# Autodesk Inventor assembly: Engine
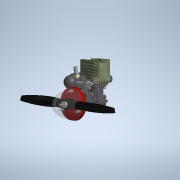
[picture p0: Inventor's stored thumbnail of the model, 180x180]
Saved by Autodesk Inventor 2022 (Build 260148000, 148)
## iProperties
Created: 2012-08
Part Number: Engine
Document SubType Name: Assembly
Designer: John
Author: John
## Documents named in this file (37)
- C:\Users\helfenj\Desktop\Ex_Files_Autodesk_Inventor_2022_Essential_Training\Exercise Files\01_Basic concepts\01_03\Engine.iam
- C:\Users\helfenj\Desktop\Ex_Files_Autodesk_Inventor_2022_Essential_Training\Exercise Files\01_Basic concepts\01_03\Engine Block.ipt
- C:\Users\helfenj\Desktop\Ex_Files_Autodesk_Inventor_2022_Essential_Training\Exercise Files\01_Basic concepts\01_03\Crankshaft.ipt
- C:\Users\helfenj\Desktop\Ex_Files_Autodesk_Inventor_2022_Essential_Training\Exercise Files\01_Basic concepts\01_03\Pulley Shaft.ipt
- C:\Users\helfenj\Desktop\Ex_Files_Autodesk_Inventor_2022_Essential_Training\Exercise Files\01_Basic concepts\01_03\Sleeve.ipt
- C:\Users\helfenj\Desktop\Ex_Files_Autodesk_Inventor_2022_Essential_Training\Exercise Files\01_Basic concepts\01_03\Piston Shaft.ipt
- C:\Users\helfenj\Desktop\Ex_Files_Autodesk_Inventor_2022_Essential_Training\Exercise Files\01_Basic concepts\01_03\Piston.ipt
- C:\Users\helfenj\Desktop\Ex_Files_Autodesk_Inventor_2022_Essential_Training\Exercise Files\01_Basic concepts\01_03\Piston Pin.ipt
- C:\Users\helfenj\Desktop\Ex_Files_Autodesk_Inventor_2022_Essential_Training\Exercise Files\01_Basic concepts\01_03\Crank Arm.ipt
- C:\Users\helfenj\Desktop\Ex_Files_Autodesk_Inventor_2022_Essential_Training\Exercise Files\01_Basic concepts\01_03\Face Plate.ipt
- C:\Users\helfenj\Desktop\Ex_Files_Autodesk_Inventor_2022_Essential_Training\Exercise Files\01_Basic concepts\01_03\washer4.ipt
- C:\Users\helfenj\Desktop\Ex_Files_Autodesk_Inventor_2022_Essential_Training\Exercise Files\01_Basic concepts\01_03\Screw Lock.ipt
- C:\Users\helfenj\Desktop\Ex_Files_Autodesk_Inventor_2022_Essential_Training\Exercise Files\01_Basic concepts\01_03\Beveled Sleeve.ipt
- C:\Users\helfenj\Desktop\Ex_Files_Autodesk_Inventor_2022_Essential_Training\Exercise Files\01_Basic concepts\01_03\Clutch Housing.ipt
- C:\Users\helfenj\Desktop\Ex_Files_Autodesk_Inventor_2022_Essential_Training\Exercise Files\01_Basic concepts\01_03\Brake Pad.ipt
- C:\Users\helfenj\Desktop\Ex_Files_Autodesk_Inventor_2022_Essential_Training\Exercise Files\01_Basic concepts\01_03\Clutch Sleeve14.ipt
- C:\Users\helfenj\Desktop\Ex_Files_Autodesk_Inventor_2022_Essential_Training\Exercise Files\01_Basic concepts\01_03\Clutch Bearing.ipt
- C:\Users\helfenj\Desktop\Ex_Files_Autodesk_Inventor_2022_Essential_Training\Exercise Files\01_Basic concepts\01_03\Clutch Sleeve11.ipt
- C:\Users\helfenj\Desktop\Ex_Files_Autodesk_Inventor_2022_Essential_Training\Exercise Files\01_Basic concepts\01_03\Carburetor.iam
- C:\Users\helfenj\Desktop\Ex_Files_Autodesk_Inventor_2022_Essential_Training\Exercise Files\01_Basic concepts\01_03\Heat Sink.ipt
- C:\Users\helfenj\Desktop\Ex_Files_Autodesk_Inventor_2022_Essential_Training\Exercise Files\01_Basic concepts\01_03\Starter Cover.ipt
- C:\Users\helfenj\Desktop\Ex_Files_Autodesk_Inventor_2022_Essential_Training\Exercise Files\01_Basic concepts\01_03\Horseshoe Clip.ipt
- C:\Users\helfenj\Desktop\Ex_Files_Autodesk_Inventor_2022_Essential_Training\Exercise Files\01_Basic concepts\01_03\ANSI B18.3 - 3-48 UNC - 0.375(31).ipt
- C:\Users\helfenj\Desktop\Ex_Files_Autodesk_Inventor_2022_Essential_Training\Exercise Files\01_Basic concepts\01_03\ANSI B18.3 - 2-56 UNC - 0.375(31).ipt
- C:\Users\helfenj\Desktop\Ex_Files_Autodesk_Inventor_2022_Essential_Training\Exercise Files\01_Basic concepts\01_03\Muffler.ipt
- C:\Users\helfenj\Desktop\Ex_Files_Autodesk_Inventor_2022_Essential_Training\Exercise Files\01_Basic concepts\01_03\ANSI B18.3 - 4-40 UNC - 0.875(31).ipt
- C:\Users\helfenj\Desktop\Ex_Files_Autodesk_Inventor_2022_Essential_Training\Exercise Files\01_Basic concepts\01_03\Muffler Tip.ipt
- C:\Users\helfenj\Desktop\Ex_Files_Autodesk_Inventor_2022_Essential_Training\Exercise Files\01_Basic concepts\01_03\Starter Handle.ipt
- C:\Users\helfenj\Desktop\Ex_Files_Autodesk_Inventor_2022_Essential_Training\Exercise Files\01_Basic concepts\01_03\ANSI B18.3 - 1-64 UNC - UNC - 0.25(1).ipt
- C:\Users\helfenj\Desktop\Ex_Files_Autodesk_Inventor_2022_Essential_Training\Exercise Files\01_Basic concepts\01_03\Clutch Prop Mount.ipt
- C:\Users\helfenj\Desktop\Ex_Files_Autodesk_Inventor_2022_Essential_Training\Exercise Files\01_Basic concepts\01_03\Prop Mount.ipt
- C:\Users\helfenj\Desktop\Ex_Files_Autodesk_Inventor_2022_Essential_Training\Exercise Files\01_Basic concepts\01_03\Prop.ipt
- C:\Users\helfenj\Desktop\Ex_Files_Autodesk_Inventor_2022_Essential_Training\Exercise Files\01_Basic concepts\01_03\Cone.ipt
- C:\Users\helfenj\Desktop\Ex_Files_Autodesk_Inventor_2022_Essential_Training\Exercise Files\01_Basic concepts\01_03\Crankshaft Cover.ipt
- C:\Users\helfenj\Desktop\Ex_Files_Autodesk_Inventor_2022_Essential_Training\Exercise Files\01_Basic concepts\01_03\ANSI B18.3 - 10-24 UNC - UNC - 0.5(1).ipt
- C:\Users\helfenj\Desktop\Ex_Files_Autodesk_Inventor_2022_Essential_Training\Exercise Files\01_Basic concepts\01_03\ANSI B18.2.2 - 1_4 - 20(3).ipt
- C:\Users\helfenj\Desktop\Ex_Files_Autodesk_Inventor_2022_Essential_Training\Exercise Files\01_Basic concepts\01_03\ASME B18.21.1 - No. 10. Carbon Steel(4).ipt
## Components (50 placed, 36 different names)
1. Engine Block:1 — Mate:1, Mate:2, Insert:1, Mate:8, Insert:2, Mate:16, Mate:21, Flush:1, Mate:42, Angle:1, Mate:43, Mate:47, Mate:49, Mate:50, Mate:51, Mate:57, Mate:58, Mate:59, Flush:3
2. Crankshaft:1 — Mate:1, Mate:2, Mate:3, Mate:4, Mate:11, Mate:13, Mate:23, Mate:24, Mate:25, Angle:6, DRIVE THIS
3. Pulley Shaft:1 — Mate:3, Mate:4, Mate:7, Mate:17, Mate:18, Mate:19
4. Sleeve:1 — Mate:7, Mate:20
5. Piston Shaft:1 — Insert:1, Mate:8, Mate:12, Mate:48
6. Piston:1 — Mate:10, Mate:12, Mate:14, Mate:15
7. Piston Pin:1 — Mate:9, Mate:10, Mate:14, Mate:15
8. Crank Arm:1 — Mate:9, Mate:11, Mate:13
9. Face Plate:1 — Insert:2, Mate:16, Mate:17, Mate:52, Mate:60, Mate:61, DRIVE THIS
10. washer4:1 — Mate:18, Mate:19, Mate:20
11. Screw Lock:1 — Mate:21, Flush:1
12. Beveled Sleeve:1 — Mate:23, Flush:2
13. Clutch Housing:1 — Mate:24, Flush:2, Mate:27, Mate:29, Mate:30, Mate:31, Mate:32, Mate:47
14. Brake Pad:1 — Mate:31, Mate:32, Tangent:2
15. Brake Pad:2 — Mate:29, Mate:30, Tangent:1, Mate:41
16. Clutch Sleeve14:1 — Mate:25, Mate:27, Mate:33, Mate:34, Mate:37, Mate:39, Mate:53, Mate:54
17. Clutch Bearing:1 — Mate:33, Mate:35
18. Clutch Prop Mount:1 — Mate:34, Mate:35, Tangent:1, Tangent:2, Mate:38, Mate:41, Mate:62, Mate:63, Mate:68
19. Clutch Bearing:2 — Mate:37, Mate:38, Mate:40
20. Clutch Sleeve11:1 — Mate:39, Mate:40
21. Carburetor:1 [sub-assembly] — Mate:42, Angle:1, Mate:43
22. Heat Sink:1 — Mate:48, Mate:49, Mate:50, Mate:51
23. Starter Cover:1 — Mate:52, Mate:60, Mate:61, Insert:13
24. Horseshoe Clip:1 — Mate:53, Mate:54
25. Muffler Tip:1 — Mate:55, Angle:2, Mate:56
26. Muffler:1 — Mate:55, Angle:2, Mate:56, Mate:57, Mate:58, Mate:59
27. Starter Handle:1 — Insert:13
28. Hexagon Socket Head Cap Screw - Inch No. 3 - 48 UNC - 3/8:1
29. Hexagon Socket Head Cap Screw - Inch No. 3 - 48 UNC - 3/8:2
30. Hexagon Socket Head Cap Screw - Inch No. 3 - 48 UNC - 3/8:3
31. Hexagon Socket Head Cap Screw - Inch No. 3 - 48 UNC - 3/8:4
32. Hexagon Socket Head Cap Screw - Inch No. 2 - 56 UNC - 3/8:1
33. Hexagon Socket Head Cap Screw - Inch No. 2 - 56 UNC - 3/8:2
34. Hexagon Socket Head Cap Screw - Inch No. 2 - 56 UNC - 3/8:3
35. Hexagon Socket Head Cap Screw - Inch No. 2 - 56 UNC - 3/8:4
36. Hexagon Socket Head Cap Screw - Inch No. 4 - 40 UNC - 7/8:1
37. Hexagon Socket Head Cap Screw - Inch No. 4 - 40 UNC - 7/8:2
38. Hexagon Socket Button Head Cap Screw - Inch 1 - 64 x 1/4:1
39. Hexagon Socket Button Head Cap Screw - Inch 1 - 64 x 1/4:2
40. Hexagon Socket Button Head Cap Screw - Inch 1 - 64 x 1/4:3
41. Hexagon Socket Button Head Cap Screw - Inch 1 - 64 x 1/4:4
42. Prop Mount:1 — Mate:62, Mate:63, Mate:64, Mate:65, Mate:66, Mate:67, Angle:4
43. Prop:1 — Mate:64, Mate:65, Angle:4, Mate:68, Angle:5, Angle:6
44. Cone:1 — Mate:66, Mate:67, Angle:5
45. Crankshaft Cover:1 — Flush:3
46. Hexagon Socket Button Head Cap Screw - Inch 10 - 24 x 1/2:1
47. Hexagon Socket Button Head Cap Screw - Inch 10 - 24 x 1/2:2
48. Hexagon Socket Button Head Cap Screw - Inch 10 - 24 x 1/2:3
49. External Tooth Lock Washer - Type A (Inch) No. 10. Carbon Steel:1 — Mate:70
50. Hex Jam Nut - Inch 1/4 - 20:1 — Mate:70
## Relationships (74: Mate 60, Angle 6, Insert 3, Flush 3, Tangent 2)
- Mate:1: Engine Block:1 ↔ Crankshaft:1
- Mate:2: Engine Block:1 ↔ Crankshaft:1
- Mate:3: Crankshaft:1 ↔ Pulley Shaft:1
- Mate:4: Crankshaft:1 ↔ Pulley Shaft:1
- Mate:7: Pulley Shaft:1 ↔ Sleeve:1
- Insert:1: Engine Block:1 ↔ Piston Shaft:1
- Mate:8: Engine Block:1 ↔ Piston Shaft:1
- Mate:9: Piston Pin:1 ↔ Crank Arm:1
- Mate:10: Piston:1 ↔ Piston Pin:1
- Mate:11: Crankshaft:1 ↔ Crank Arm:1
- Mate:12: Piston Shaft:1 ↔ Piston:1
- Mate:13: Crankshaft:1 ↔ Crank Arm:1
- Mate:14: Piston:1 ↔ Piston Pin:1
- Mate:15: Piston:1 ↔ Piston Pin:1
- Insert:2: Engine Block:1 ↔ Face Plate:1
- Mate:16: Engine Block:1 ↔ Face Plate:1
- Mate:17: Pulley Shaft:1 ↔ Face Plate:1
- Mate:18: Pulley Shaft:1 ↔ washer4:1
- Mate:19: Pulley Shaft:1 ↔ washer4:1
- Mate:20: Sleeve:1 ↔ washer4:1
- Mate:21: Engine Block:1 ↔ Screw Lock:1
- Flush:1: Engine Block:1 ↔ Screw Lock:1
- Mate:23: Crankshaft:1 ↔ Beveled Sleeve:1
- Mate:24: Crankshaft:1 ↔ Clutch Housing:1
- Flush:2: Beveled Sleeve:1 ↔ Clutch Housing:1
- Mate:25: Crankshaft:1 ↔ Clutch Sleeve14:1
- Mate:27: Clutch Housing:1 ↔ Clutch Sleeve14:1
- Mate:29: Clutch Housing:1 ↔ Brake Pad:2
- Mate:30: Clutch Housing:1 ↔ Brake Pad:2
- Mate:31: Clutch Housing:1 ↔ Brake Pad:1
- Mate:32: Clutch Housing:1 ↔ Brake Pad:1
- Mate:33: Clutch Sleeve14:1 ↔ Clutch Bearing:1
- Mate:34: Clutch Sleeve14:1 ↔ Clutch Prop Mount:1
- Mate:35: Clutch Bearing:1 ↔ Clutch Prop Mount:1
- Tangent:1: Brake Pad:2 ↔ Clutch Prop Mount:1
- Tangent:2: Brake Pad:1 ↔ Clutch Prop Mount:1
- Mate:37: Clutch Sleeve14:1 ↔ Clutch Bearing:2
- Mate:38: Clutch Prop Mount:1 ↔ Clutch Bearing:2
- Mate:39: Clutch Sleeve14:1 ↔ Clutch Sleeve11:1
- Mate:40: Clutch Bearing:2 ↔ Clutch Sleeve11:1
- Mate:41: Brake Pad:2 ↔ Clutch Prop Mount:1
- Mate:42: Engine Block:1 ↔ Carburetor:1
- Angle:1: Engine Block:1 ↔ Carburetor:1
- Mate:43: Engine Block:1 ↔ Carburetor:1
- Mate:47: Engine Block:1 ↔ Clutch Housing:1
- Mate:48: Piston Shaft:1 ↔ Heat Sink:1
- Mate:49: Engine Block:1 ↔ Heat Sink:1
- Mate:50: Engine Block:1 ↔ Heat Sink:1
- Mate:51: Engine Block:1 ↔ Heat Sink:1
- Mate:52: Face Plate:1 ↔ Starter Cover:1
- Mate:53: Clutch Sleeve14:1 ↔ Horseshoe Clip:1
- Mate:54: Clutch Sleeve14:1 ↔ Horseshoe Clip:1
- Mate:55: Muffler Tip:1 ↔ Muffler:1
- Angle:2: Muffler Tip:1 ↔ Muffler:1
- Mate:56: Muffler Tip:1 ↔ Muffler:1
- Mate:57: Engine Block:1 ↔ Muffler:1
- Mate:58: Engine Block:1 ↔ Muffler:1
- Mate:59: Engine Block:1 ↔ Muffler:1
- Mate:60: Face Plate:1 ↔ Starter Cover:1
- Mate:61: Face Plate:1 ↔ Starter Cover:1
- Insert:13: Starter Cover:1 ↔ Starter Handle:1
- Angle:6: Crankshaft:1 ↔ Prop:1
- DRIVE THIS [Angle]: Crankshaft:1 ↔ Face Plate:1
- Mate:62: Clutch Prop Mount:1 ↔ Prop Mount:1
- Mate:63: Clutch Prop Mount:1 ↔ Prop Mount:1
- Mate:64: Prop Mount:1 ↔ Prop:1
- Mate:65: Prop Mount:1 ↔ Prop:1
- Mate:66: Prop Mount:1 ↔ Cone:1
- Mate:67: Prop Mount:1 ↔ Cone:1
- Angle:4: Prop Mount:1 ↔ Prop:1
- Mate:68: Clutch Prop Mount:1 ↔ Prop:1
- Angle:5: Prop:1 ↔ Cone:1
- Flush:3: Engine Block:1 ↔ Crankshaft Cover:1
- Mate:70: External Tooth Lock Washer - Type A (Inch) No. 10. Carbon Steel:1 ↔ Hex Jam Nut - Inch 1/4 - 20:1
